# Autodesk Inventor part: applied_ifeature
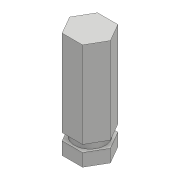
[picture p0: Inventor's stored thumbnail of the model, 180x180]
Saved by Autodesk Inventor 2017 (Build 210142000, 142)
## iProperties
Created: 2016-08
Part Number: applied_ifeature
Material: Generic
Document SubType Name: Modeling
Designer: Sandeep
Density: 1 g/cm^3
Appearance: Default
Author: Sandeep
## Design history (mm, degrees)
sketch "Sketch1"
  geometry: L1 (28.868, 0)-(14.434, -25); L2 (14.434, -25)-(-14.434, -25); L3 (-14.434, -25)-(-28.868, 0); L4 (-28.868, 0)-(-14.434, 25); L5 (-14.434, 25)-(14.434, 25); L6 (14.434, 25)-(28.868, 0); 2 further points
  constraints: 12 end point, 1 coincident, 13 other
  dimensions: "d0" = 50 distance between parallel lines of L2 L5
extrude "Extrusion1" new body sketch "Sketch1" distance "d1" = 150; taper "d2" = 0 deg
feature "iFeature4:1"
body "Solid1"
